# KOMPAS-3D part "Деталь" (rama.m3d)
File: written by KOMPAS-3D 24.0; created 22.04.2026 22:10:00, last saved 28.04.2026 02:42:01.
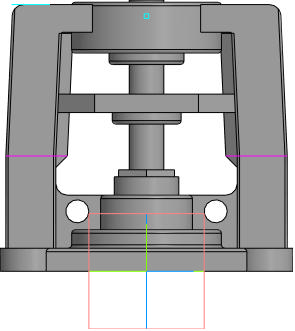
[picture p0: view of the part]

Document properties: Автор: mrdid; Полное имя файла: C:\Работа\ГОТОВЫЕ ИСХОДНИКИ\VSO2130M-F-S Клапан запорный сильфонный DN.ru Ду15-100 Ру40\исходные материалы\DN65\rama.m3d

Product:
- Part/product: Деталь
    Масса: 4.073007

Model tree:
1. Эскиз:2  (with: Ребро.Элемент выдавливания:14)
2. Элемент выдавливания:1
     Расстояние 1 = 10
3. Эскиз:3  (with: Грань.Элемент выдавливания:1, Ребро.Элемент выдавливания:1)
4. Элемент выдавливания:2
     Расстояние 2 = 10
5. Эскиз:4  (with: Грань.Элемент выдавливания:1)
6. Элемент выдавливания:3
     Расстояние 1 = 8
7. Эскиз:5  (with: Грань.Элемент выдавливания:3, Ребро.Элемент выдавливания:3)
8. Элемент выдавливания:4
     Расстояние 1 = 15
9. Эскиз:6  (with: Грань.Элемент выдавливания:1, Ребро.Элемент выдавливания:1)
10. Элемент выдавливания:5
     Расстояние 1 = 40
11. Эскиз:23  (with: Грань.Элемент выдавливания:4, Ребро.Элемент выдавливания:4)
12. Элемент выдавливания:21
     Расстояние 1 = 11
13. Эскиз:7  (with: Грань.Элемент выдавливания:21, Ребро.Элемент выдавливания:3)
14. Элемент выдавливания:6
     Расстояние 2 = 3
15. Эскиз:8  (with: Грань.Элемент выдавливания:5, Ребро.Элемент выдавливания:5)
16. Смещенная плоскость:1  (with: Грань.Элемент выдавливания:5)
17. Эскиз:9
18. Элемент по сечениям:1
19. Элемент по сечениям:2
20. Эскиз:10
21. Элемент выдавливания:8
     Расстояние 2 = 12
22. Эскиз:11  (with: Грань.Элемент выдавливания:8, Ребро.Элемент выдавливания:3)
23. Элемент выдавливания:9  (with: Грань.Элемент выдавливания:8)
     Расстояние 1 = 1; Расстояние 2 = 21; Смещение 2 = 9
24. Эскиз:12  (with: Грань.Элемент выдавливания:9, Ребро.Элемент выдавливания:9)
25. Элемент выдавливания:10
     Расстояние 1 = 5
26. Эскиз:13  (with: Грань.Элемент выдавливания:21, Ребро.Элемент выдавливания:3)
27. Элемент выдавливания:11  (with: Грань.Элемент выдавливания:10)
     Расстояние 1 = 45.64
28. Смещенная плоскость:2  (with: Грань.Элемент выдавливания:21)
29. Эскиз:14  (with: Ребро.Элемент по сечениям:2, Ребро.Элемент по сечениям:1)
30. Элемент выдавливания:12
     Расстояние 1 = 8
31. Эскиз:15  (with: Грань.Элемент выдавливания:12, Ребро.Элемент выдавливания:3)
32. Элемент выдавливания:13
     Расстояние 1 = 5
33. Эскиз:16  (with: Ребро.Элемент выдавливания:5, Ребро.Элемент выдавливания:1, Ребро.Элемент выдавливания:4)
34. Элемент выдавливания:14
     Расстояние 1 = 4
35. Элемент выдавливания:15
     Расстояние 1 = 2
36. Эскиз:17  (with: Ребро.Элемент выдавливания:14, Ребро.Элемент выдавливания:5)
37. Элемент выдавливания:16
     Расстояние 1 = 63.5
38. Скругление:1  (with: Ребро.Элемент выдавливания:1, Ребро.Элемент выдавливания:3)
     Радиус = 1.5
39. Скругление:2  (with: Ребро.Элемент выдавливания:9, Ребро.Элемент выдавливания:13, Ребро.Элемент выдавливания:4, Ребро.Элемент выдавливания:10)
40. Эскиз:18  (with: Грань.Элемент выдавливания:9)
41. Элемент выдавливания:17
     Расстояние 1 = 1
42. Скругление:3  (with: Ребро.Элемент по сечениям:2, Ребро.Элемент по сечениям:1)
     Радиус = 5
43. Скругление:4  (with: Ребро.Элемент выдавливания:8)
     Радиус = 0.5
44. Скругление:5  (with: Ребро.Элемент выдавливания:14)
     Радиус = 5
45. Эскиз:19  (with: Ребро.Элемент выдавливания:17)
46. Элемент выдавливания:18  (with: Грань.Элемент выдавливания:9)
     Смещение 1 = 5
47. Смещенная плоскость:3  (with: Грань.Элемент выдавливания:18)
     Расстояние = 2
48. Эскиз:20  (with: Ребро.Элемент выдавливания:18)
49. Элемент выдавливания:19
     Расстояние 2 = 0.2
50. Скругление:6  (with: Ребро.Элемент выдавливания:18)
     Радиус = 1
51. Эскиз:21  (with: Ребро.Элемент выдавливания:19)
52. Элемент выдавливания:20
     Расстояние 1 = 10
53. Скругление:7  (with: Ребро.Элемент по сечениям:2, Ребро.Элемент выдавливания:5, Ребро.Элемент по сечениям:1)
     Радиус = 1
54. Фаска:1  (with: Ребро.Элемент по сечениям:1, Ребро.Элемент по сечениям:2)
     Угол = 45; Длина 1 = 5; Длина 2 = 5
55. Массив по концентрической сетке:1  (with: Элемент выдавливания:2, Эскиз:3)  (labels: Клапан запорный DN.ru Ду65 Ру40)  (4 pattern instances)
     Шаг 2 = 360

Expressions: DN/2; v249/2; DN/3
Referenced files in C:\Работа\ГОТОВЫЕ ИСХОДНИКИ\VSO2130M-F-S Клапан запорный сильфонный DN.ru Ду15-100 Ру40\исходные материалы\DN65\: VSO2130M-F-S Клапан запорный DN.ru Ду65 Ру40.a3d
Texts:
  DN+5
  DN-20
  Ось Y.Начало координат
